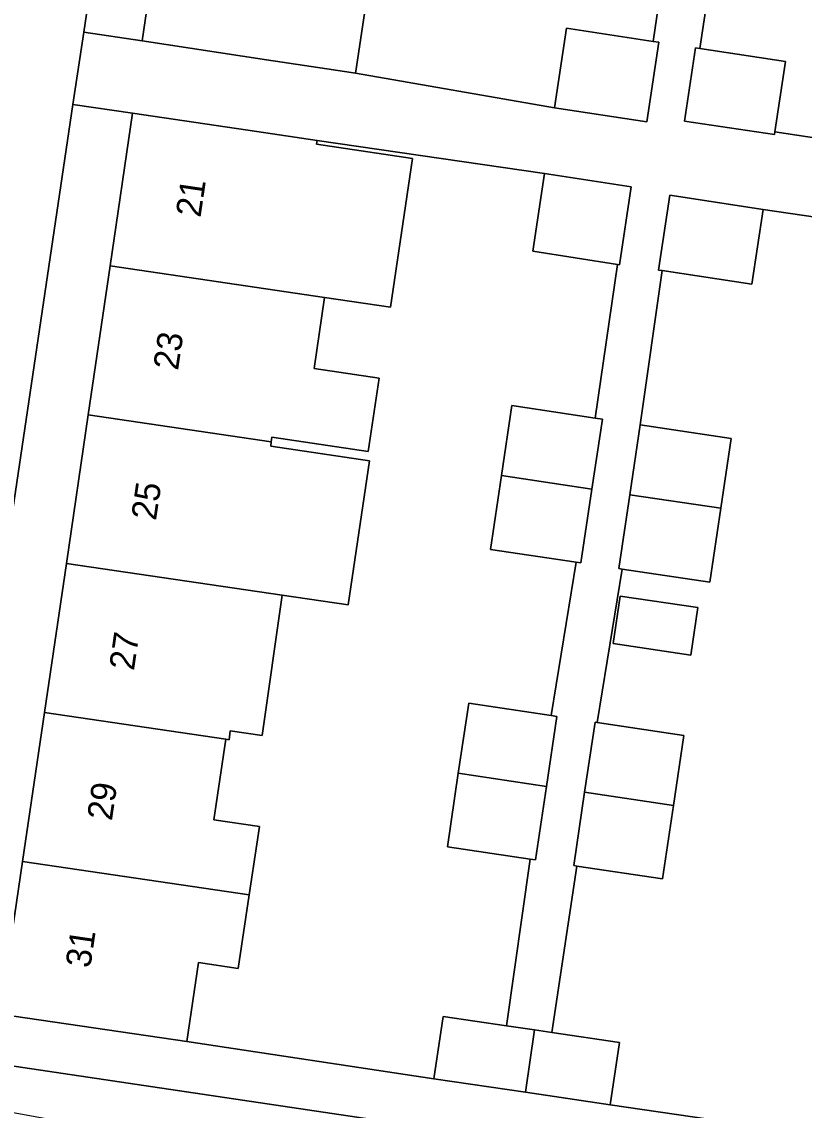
# Model space of a CAD drawing. Extents: x 163683 to 164494, y 382709 to 383872.
# Drawn here: x 164096.84 to 164127.96, y 382929.41 to 382972.71 of the extents above; entities that cross this region are included whole.
import ezdxf

# ---------------------------------------------------------------- set-up
doc = ezdxf.new("R2010")
doc.units = 0
for name, color, linetype in [('IMGEO_Erf', 7, 'Continuous'), ('IMGEO_Groenvoorziening', 7, 'Continuous'), ('IMGEO_Pand', 7, 'Continuous'), ('IMGEO_Pand_nummerreeks', 7, 'Continuous'), ('IMGEO_Voetpad_open', 7, 'Continuous')]:
    doc.layers.add(name, color=color, linetype=linetype)

msp = doc.modelspace()

# ---------------------------------------------------------------- linework, layer by layer
at = {"layer": 'IMGEO_Erf'}
for points in [[(164104.286, 382989.96), (164105.163, 382995.903), (164105.767, 383000), (164106.04, 383001.847), (164106.933, 383007.903), (164104.762, 383008.256), (164103.418, 383000), (164099.302, 382972.288), (164101.628, 382971.943), (164102.532, 382978.072), (164103.409, 382984.016)], [(164099.481, 382957.073), (164100.351, 382962.995), (164101.242, 382969.066), (164098.876, 382969.417), (164093.559, 382933.622), (164095.981, 382933.235), (164096.872, 382939.305), (164097.742, 382945.228), (164098.612, 382951.157)], [(164118.888, 382951.206), (164115.482, 382951.715), (164115.92, 382954.655), (164116.336, 382957.436), (164119.642, 382956.943), (164120.528, 382963.053), (164117.168, 382963.585), (164117.634, 382966.665), (164108.585, 382967.987), (164108.563, 382967.836), (164112.382, 382967.271), (164111.508, 382961.357), (164108.884, 382961.742), (164108.465, 382958.91), (164111.052, 382958.528), (164110.621, 382955.611), (164106.787, 382956.178), (164106.764, 382956.002), (164106.741, 382955.828), (164110.675, 382955.247), (164109.827, 382949.509), (164107.201, 382949.895), (164106.406, 382944.311), (164105.133, 382944.499), (164105.081, 382944.15), (164104.954, 382944.169), (164104.484, 382940.966), (164106.288, 382940.698), (164106.184, 382939.997), (164105.883, 382937.98), (164105.446, 382935.051), (164103.863, 382935.283), (164103.402, 382932.145), (164113.229, 382930.665), (164113.595, 382933.142), (164116.124, 382932.768), (164117.062, 382939.396), (164113.765, 382939.888), (164114.202, 382942.813), (164114.617, 382945.596), (164117.894, 382945.107)], [(164123.452, 382947.515), (164120.358, 382947.977), (164120.639, 382949.863), (164123.733, 382949.401)]]:
    msp.add_lwpolyline(points, close=True, dxfattribs=at)
for points in [[(164110.609, 382973.941), (164110.151, 382970.913), (164110.113, 382970.66), (164118.03, 382969.286), (164118.508, 382972.447), (164121.958, 382971.925), (164122.87, 382978.172)], [(164124.755, 382977.888), (164123.807, 382971.646), (164127.214, 382971.131), (164126.79, 382968.33), (164131.776, 382967.569), (164131.811, 382967.807), (164132.27, 382970.928), (164132.669, 382973.639)], [(164136.023, 382963.821), (164126.324, 382965.242), (164125.874, 382962.269), (164122.312, 382962.808), (164121.437, 382956.675), (164125.056, 382956.135), (164124.641, 382953.354), (164124.202, 382950.413), (164120.723, 382950.932), (164119.722, 382944.835), (164123.176, 382944.32), (164122.761, 382941.537), (164122.324, 382938.611), (164118.918, 382939.12), (164117.92, 382932.502), (164120.608, 382932.105), (164120.241, 382929.628), (164128.706, 382928.397)]]:
    msp.add_lwpolyline(points, dxfattribs=at)
at = {"layer": 'IMGEO_Groenvoorziening'}
for points in [[(164093.559, 382933.622), (164093.297, 382931.638), (164139.939, 382924.7), (164140.229, 382926.679), (164137.706, 382927.054), (164130.289, 382928.161), (164128.706, 382928.397), (164120.241, 382929.628), (164116.872, 382930.126), (164113.229, 382930.665), (164103.402, 382932.145), (164095.981, 382933.235)], [(164093.297, 382931.638), (164093.072, 382929.933), (164094.036, 382929.771), (164105.912, 382927.595), (164116.325, 382925.558), (164136.589, 382920.625), (164138.954, 382920.045), (164139.409, 382922.626), (164139.939, 382924.7)]]:
    msp.add_lwpolyline(points, close=True, dxfattribs=at)
at = {"layer": 'IMGEO_Pand'}
for points in [[(164110.609, 382973.941), (164111.038, 382976.781), (164102.532, 382978.072), (164101.628, 382971.943), (164106.572, 382971.195), (164108.967, 382970.833), (164110.113, 382970.66), (164110.151, 382970.913)], [(164122.178, 382971.892), (164121.958, 382971.925), (164118.508, 382972.447), (164118.03, 382969.286), (164121.7, 382968.731)], [(164123.807, 382971.646), (164123.632, 382971.673), (164123.192, 382968.757), (164126.773, 382968.216), (164126.79, 382968.33), (164127.214, 382971.131)], [(164108.563, 382967.836), (164108.585, 382967.987), (164106.189, 382968.339), (164101.242, 382969.066), (164100.351, 382962.995), (164108.884, 382961.742), (164111.508, 382961.357), (164112.382, 382967.271)], [(164117.634, 382966.665), (164117.168, 382963.585), (164120.528, 382963.053), (164120.607, 382963.04), (164121.076, 382966.145)], [(164126.324, 382965.242), (164122.617, 382965.803), (164122.167, 382962.83), (164122.312, 382962.808), (164125.874, 382962.269)], [(164108.884, 382961.742), (164100.351, 382962.995), (164099.481, 382957.073), (164106.764, 382956.002), (164106.787, 382956.178), (164110.621, 382955.611), (164111.052, 382958.528), (164108.465, 382958.91)], [(164119.642, 382956.943), (164116.336, 382957.436), (164115.92, 382954.655), (164119.515, 382954.119), (164119.93, 382956.9)], [(164106.741, 382955.828), (164106.764, 382956.002), (164099.481, 382957.073), (164098.612, 382951.157), (164107.201, 382949.895), (164109.827, 382949.509), (164110.675, 382955.247)], [(164121.437, 382956.675), (164121.022, 382953.894), (164124.641, 382953.354), (164125.056, 382956.135)], [(164119.515, 382954.119), (164115.92, 382954.655), (164115.482, 382951.715), (164118.888, 382951.206), (164119.076, 382951.178)], [(164124.641, 382953.354), (164121.022, 382953.894), (164120.583, 382950.953), (164120.723, 382950.932), (164124.202, 382950.413)], [(164107.201, 382949.895), (164098.612, 382951.157), (164097.742, 382945.228), (164104.954, 382944.169), (164105.081, 382944.15), (164105.133, 382944.499), (164106.406, 382944.311)], [(164120.358, 382947.977), (164123.452, 382947.515), (164123.733, 382949.401), (164120.639, 382949.863)], [(164117.894, 382945.107), (164114.617, 382945.596), (164114.202, 382942.813), (164117.707, 382942.291), (164118.122, 382945.073)], [(164104.954, 382944.169), (164097.742, 382945.228), (164096.872, 382939.305), (164105.883, 382937.98), (164106.184, 382939.997), (164106.288, 382940.698), (164104.484, 382940.966)], [(164119.722, 382944.835), (164119.641, 382944.847), (164119.226, 382942.064), (164122.761, 382941.537), (164123.176, 382944.32)], [(164117.707, 382942.291), (164114.202, 382942.813), (164113.765, 382939.888), (164117.062, 382939.396), (164117.271, 382939.365)], [(164122.761, 382941.537), (164119.226, 382942.064), (164118.79, 382939.139), (164118.918, 382939.12), (164122.324, 382938.611)], [(164096.872, 382939.305), (164095.981, 382933.235), (164103.402, 382932.145), (164103.863, 382935.283), (164105.446, 382935.051), (164105.883, 382937.98)], [(164117.233, 382932.604), (164116.124, 382932.768), (164113.595, 382933.142), (164113.229, 382930.665), (164116.872, 382930.126)], [(164120.608, 382932.105), (164117.92, 382932.502), (164117.233, 382932.604), (164116.872, 382930.126), (164120.241, 382929.628)]]:
    msp.add_lwpolyline(points, close=True, dxfattribs=at)
at = {"layer": 'IMGEO_Voetpad_open'}
for points in [[(164088.947, 382922.357), (164088.832, 382921.684), (164088.61, 382920.207), (164091.557, 382919.741), (164092.722, 382927.559), (164093.072, 382929.933), (164093.297, 382931.638), (164093.559, 382933.622), (164098.876, 382969.417), (164099.302, 382972.288), (164103.418, 383000), (164104.762, 383008.256), (164105.063, 383010.105), (164103.379, 383010.362), (164103.936, 383014.016), (164105.713, 383025.977)], [(164122.87, 382978.172), (164121.958, 382971.925), (164122.178, 382971.892), (164121.7, 382968.731), (164118.03, 382969.286), (164110.113, 382970.66), (164108.967, 382970.833), (164106.572, 382971.195), (164101.628, 382971.943), (164099.302, 382972.288), (164098.876, 382969.417), (164101.242, 382969.066), (164106.189, 382968.339), (164108.585, 382967.987), (164117.634, 382966.665), (164121.076, 382966.145), (164120.607, 382963.04), (164120.528, 382963.053), (164119.642, 382956.943), (164119.93, 382956.9), (164119.515, 382954.119), (164119.076, 382951.178), (164118.888, 382951.206), (164117.894, 382945.107), (164118.122, 382945.073), (164117.707, 382942.291), (164117.271, 382939.365), (164117.062, 382939.396), (164116.124, 382932.768), (164117.233, 382932.604), (164117.92, 382932.502), (164118.918, 382939.12), (164118.79, 382939.139), (164119.226, 382942.064), (164119.641, 382944.847), (164119.722, 382944.835), (164120.723, 382950.932), (164120.583, 382950.953), (164121.022, 382953.894), (164121.437, 382956.675), (164122.312, 382962.808), (164122.167, 382962.83), (164122.617, 382965.803), (164126.324, 382965.242), (164136.023, 382963.821)], [(164131.776, 382967.569), (164126.79, 382968.33), (164126.773, 382968.216), (164123.192, 382968.757), (164123.632, 382971.673), (164123.807, 382971.646), (164124.755, 382977.888)]]:
    msp.add_lwpolyline(points, dxfattribs=at)

# ---------------------------------------------------------------- texts
at = {"layer": 'IMGEO_Pand_nummerreeks'}
for s, rotation, p in [('21', 81.6465, (164103.946, 382964.898)), ('23', 81.6465, (164103.052, 382958.814)), ('25', 81.6465, (164102.175, 382952.842)), ('27', 81.6465, (164101.298, 382946.87)), ('29', 81.6465, (164100.421, 382940.898)), ('31', 81.647, (164099.562, 382935.039))]:
    msp.add_text(s, height=1, rotation=rotation, dxfattribs=at).set_placement(p)

doc.saveas('drawing.dxf')
